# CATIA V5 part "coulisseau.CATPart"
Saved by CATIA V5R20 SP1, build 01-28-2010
Part number: coulisseau
Bounding box of the stored display mesh (mm): x -155 to -150, y 0 to 5, z 70 to 75
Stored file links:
  E:\EDELI\gcausse\Edeli_2012_190_gcausse\coulisseau.CATPart
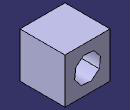
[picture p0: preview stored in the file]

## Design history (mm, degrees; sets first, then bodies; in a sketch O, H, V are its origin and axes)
Body1 (main body)
  Sketch1 on zx-plane, origin (0, 0, 0), H (-1, 0, 0), V (0, 0, 1)
    line L1 (150, 75) -> (155, 75)
    line L2 (155, 75) -> (155, 70)
    line L3 (155, 70) -> (150, 70)
    line L4 (150, 70) -> (150, 75)
    distance L4 L2 = 5
    distance L1 L3 = 5
    horizontal: L1 H, L3 H
    vertical: L2 V, L4 V
  Pad1: profile Sketch1, direction (0, 1, 0), length 5
  Sketch2 on end face of Pad1, origin (0, 5, 0), H (-1, 0, 0), V (0, 0, 1)
  Sketch3 on end face of Pad1, origin (-153.1752, 5, 73.6926), H (1, 0, 0), V (0, 0, -1)
    point P1 (0.6752, 1.1926)
    reference projected line E1 (3.1752, 3.6926) -> (-1.8248, 3.6926) from edge [face of Pad1 from Sketch1.L3 | end face of Pad1]
    reference projected line E2 (3.1752, -1.3074) -> (3.1752, 3.6926) from edge [face of Pad1 from Sketch1.L4 | end face of Pad1]
    distance P1 E1 = 2.5
    distance P1 E2 = 2.5
  Hole1: placed by Sketch3, at (-152.5, 5, 72.5) direction (0, -1, 0), diameter 3, depth 10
